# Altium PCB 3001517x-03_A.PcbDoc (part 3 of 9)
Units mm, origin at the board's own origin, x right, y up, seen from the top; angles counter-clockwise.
Board outline 100 x 72 mm, 10 copper layers (Top, GND_2, Signal_3, Signal_4, PWR_5, GND_6, Signal_7, Signal_8, GND_9, Bottom), stack 1.6 mm thick; 602 components, 497 nets, 2372 pads, 1602 vias.
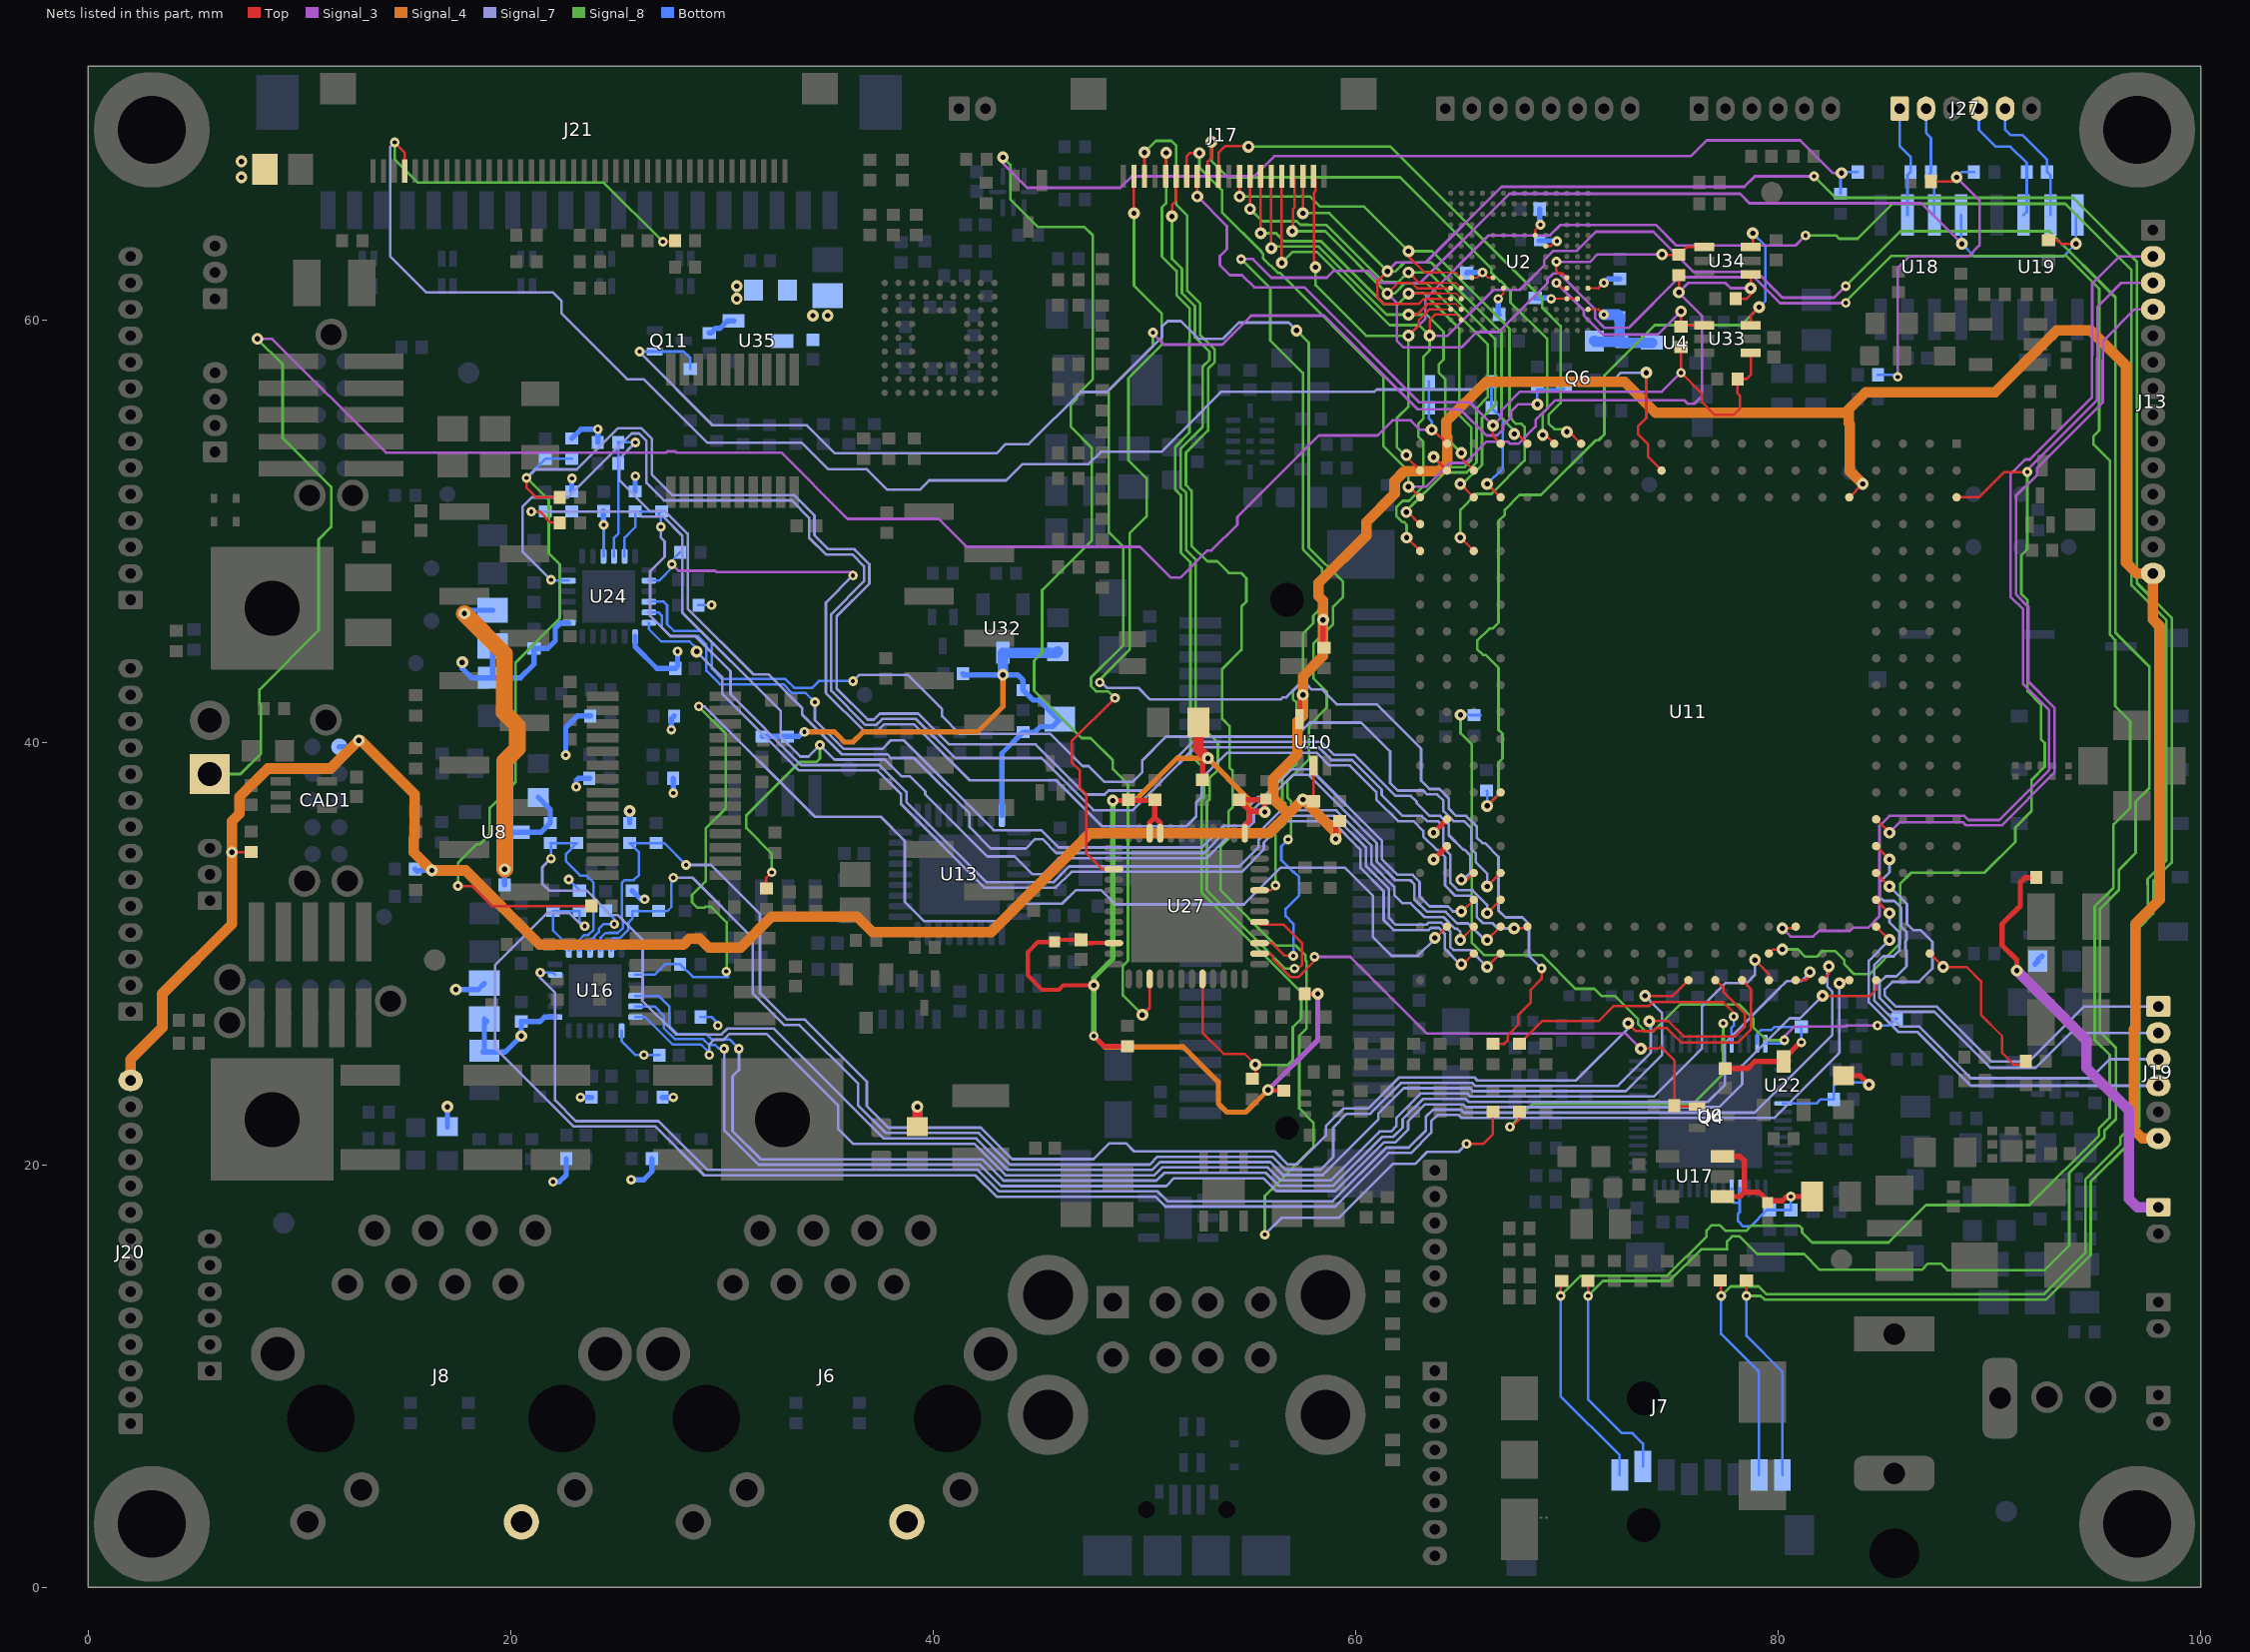
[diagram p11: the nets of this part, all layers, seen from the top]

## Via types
v1: diameter 0.56, hole 0.25, Top to Bottom, tented both sides, 1002 vias
v2: diameter 0.46, hole 0.2, Top to Bottom, tented both sides, 468 vias
v3: diameter 0.457, hole 0.2, Top to Bottom, tented both sides, 132 vias

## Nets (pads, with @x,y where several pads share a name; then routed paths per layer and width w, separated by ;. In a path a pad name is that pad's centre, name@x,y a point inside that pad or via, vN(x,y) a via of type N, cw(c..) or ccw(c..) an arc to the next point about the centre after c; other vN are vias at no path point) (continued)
3V3_CODEC: C87.1 C89.1 C98.2 C102.1 C103.1 C129.2 C149.2 R206.2 U6.6 U6.18 U6.19 U6.55 U17.1 U17.3 U22.D | length 27.4
  Top w0.25: U17.1@77.358,18.5 78.2,18.5 78.4,18.7 ; U17.3@77.358,20.4 78.2,20.4 78.4,20.2 78.4,18.7 ; C149.2@77.5,24.56 78.56,24.56 78.9,24.9 U22.D@80.258,24.9 80.258,25.008 81.05,25.8 v2(81.1,25.8) ; C98.2@81.6,18.5 81.4,18.7 81.2,18.5 v2(80.6,18.5) 80.4,18.5 80.2,18.3 79.5,18.3 79.1,18.7 78.4,18.7 ; R206.2@83.1,24.218 83.882,24.218 v1(84.3,23.8)
  Bottom w0.125: U6.19@77.8,18.88 77.8,18.309 77.909,18.2 78.13,18.2 78.18,18.25 ; U6.18@78.2,18.88 78.18,18.88 78.18,18.25 ; U6.55@79,25.74 79,26.2 79.18,26.38 79.674,26.38 79.814,26.521 81.08,26.521 C89.1@81.1,26.54 ; U6.6@80.23,22.91 81.81,22.91 82,23.1 C87.1@82.64,23.1 82.64,23.74 82.8,23.9 84.2,23.9 v1(84.3,23.8) ; v2(80.6,18.5) C102.1@80.6,17.86 C103.1@79.6,17.86 79.467,17.86 78.7,17.094 78.35,17.094 78.104,17.339 78.104,17.687 78.18,17.763 78.18,18.25 ; v2(81.1,25.8) 81.1,26.499 C89.1@81.101,26.5
3V3_EMMC: C4.2 C5.2 C6.2 C7.2 C24.2 C126.2 C127.2 C128.2 R223.2 U2.C6 U2.E6 U2.F5 U2.J10 U2.K9 U2.M4 U2.N4 U2.P3 U2.P5 U4.D | length 15.5
  Top w0.076: U2.P3@71,60.5 71.5,60.5 ; U2.P5@71,61.5 71.5,61.5
  Top w0.1: U2.C6@65.5,62 65.75,62 v2(66,62.25) 66.25,62 U2.E6@66.5,62 ; v2(66.75,61) 67,61.25 U2.F5@67,61.5 ; U2.J10@68.5,64 68.5,64.25 v2(68.75,64.5) ; U2.K9@69,63.5 69.25,63.5 69.476,63.726 v2(69.524,63.726) ; v2(69.25,61) U2.M4@70,61 U2.N4@70.5,61
  Top w0.125: 71.5,60.5 v2(71.75,60.25) ; 71.5,61.5 v2(71.75,61.75)
  Bottom w0.25: C128.2@65.25,62.21 65.29,62.25 v2(66,62.25) ; v2(66.75,61) 66.75,60.29 C127.2@66.79,60.25 ; C5.2@68.5,61.04 69.21,61.04 v2(69.25,61) ; C126.2@68.69,63.75 69.5,63.75 v2(69.524,63.726) ; C4.2@68.71,65.25 68.71,64.54 v2(68.75,64.5) ; v2(71.75,61.75) 71.94,61.94 C6.2@72.5,61.94
  Bottom w0.5: R223.2@71.3,59 71.34,58.96 C24.2@72.6,58.96 ; v2(71.75,60.25) 72.41,60.25 C7.2@72.5,60.16 72.5,59.06 C24.2@72.6,58.96 ; U4.D@74.02,58.92 72.64,58.92 C24.2@72.6,58.96
3V3_ETH: C26.2 C28.1 C46.1 L2.1 L3.1 R26.1 R27.2 R56.1 R57.1 R58.1 R59.1 R90.1 R158.1 R159.1 R160.1 R161.1 U8.D U16.9 U24.9 | length 34.3
  Signal_4 w0.8: v1(17.8,46.1) 19.7,44.2 19.7,41.4 20.3,40.8 20.3,39.7 19.71,39.11 v1(19.71,34)
  Bottom w0.125: v2(22.742,33.516) 23.25,33.008 R59.1@23.25,32.98 ; U16.9@23.75,30.15 23.75,30.609 24.166,31.024 24.166,31.166 24.4,31.4 v2(24.9,31.4) 24.9,31.64 C28.1@24.5,32.04 ; U24.9@24.389,48.807 24.4,48.818 v2(24.4,50.3) ; R90.1@28.88,46.5 v2(29.5,46.5) ; R26.1@28.98,27 29.5,27 29.8,26.7 v2(29.8,26.6)
  Bottom w0.25: v1(17.4,28.3) 18.45,28.3 L2.1@18.75,28.6 ; v1(17.8,46.1) 17.957,46.257 L3.1@19.139,46.257 ; C26.2@19.71,33.25 v1(19.71,34) 19.71,35.31 20.15,35.75 U8.D@20.375,35.75 21.434,35.75 R58.1@21.873,36.189 21.873,36.827 R27.2@21.3,37.4 ; R161.1@22.889,51.887 22.889,52.489 v2(22.9,52.5) ; R160.1@22.889,54.387 23.322,54.82 v2(24.12,54.82) R158.1@24.12,54.2 ; C46.1@24.389,50.947 24.389,50.311 v2(24.4,50.3) ; R56.1@25.623,36.189 v1(25.623,36.75) ; R57.1@25.75,32.98 26.157,32.573 v2(26.333,32.573) ; R159.1@25.889,51.887 v2@25.889,52.5
  other v2: 25.9,52.6
3V3_INT: C150.2 CAD1.1 J13.14 J19.6 J20.14 R36.2 R149.1 R231.1 R260.1 U10.3 U10.5 U11.E3 | length 190.9
  Top w0.125: v1(6.8,34.8) 7.68,34.8 R36.2@7.7,34.82 ; v1(57.5,37.3) 57.91,37.3 C150.2@58,37.21 U10.5@58,38.9 ; U11.E3@83.37,51.6 v1(84.005,52.235)
  Top w0.25: U10.3@57.35,41.1 57.35,42.1 v1(57.5,42.25) ; R231.1@58.458,44.48 v1(58.458,45.8) ; v1(59.055,35.427) 59.055,36.075 R260.1@59.25,36.27
  Signal_4 w0.5: J20.14@2,23.75 2,25 3.5,26.5 3.5,28.1 6.8,31.4 v1(6.8,34.8) 6.8,36.271 7.157,36.628 7.157,37.417 8.5,38.76 11.46,38.76 v1(12.8,40.1) 12.9,40.1 15.457,37.543 15.457,35.528 15.4,35.471 15.4,34.8 v1(16.261,33.939) 17.861,33.939 21.363,30.436 28.178,30.436 28.449,30.707 28.951,30.707 29.365,30.293 30.885,30.293 32.342,31.75 36.392,31.75 37.131,31.01 42.74,31.01 47.439,35.709 55.909,35.709 56.82,36.62 ; v1(59.055,35.427) 59.055,35.744 v1(57.5,37.3) 56.82,36.62 ; v1(84.005,52.235) 83.392,52.848 83.392,55.047 83.335,55.105 83.343,55.113 83.343,55.772 ; J19.6@98,21.25 97.248,21.25 96.85,21.648 96.85,26.421 96.907,26.478 96.907,31.407 98.062,32.562 98.062,45.5 97.75,45.812 J13.14@97.75,48 96.985,48 96.477,48.508 96.477,57.823 94.8,59.5 93.194,59.5 90.272,56.578 84.149,56.578 83.343,55.772 ; 56.82,36.62 56.1,37.34 56.1,38.278 57.25,39.428 57.25,41 57.5,41.25 v1(57.5,42.25) 57.5,43.125 58.458,44.083 v1(58.458,45.8) 58.458,46.713 58.243,46.928 58.243,47.543 60.5,49.8 60.5,50.429 61.843,51.772 61.843,52.372 62.319,52.848 63.957,52.848 64.342,53.233 64.342,54.459 64.298,54.503 64.298,55.198 66.176,57.077 72.723,57.077 74.2,55.6 83.171,55.6 83.343,55.772
  Bottom w0.25: CAD1.1@11.885,39.79 12.49,39.79 v1(12.8,40.1) ; R149.1@15.472,34 15.572,33.9 15.611,33.939 v1(16.261,33.939)
3V3_IOEXP: C104.2 C105.2 C106.2 C120.2 C122.2 C124.2 R232.1 R247.2 R262.2 R265.2 R280.2 U27.1 U27.9 U27.10 U27.22 | length 61.2
  Top w0.2: v1(47.6,28.5) 46.154,28.5 45.947,28.293 45.155,28.293 44.484,28.964 44.484,30.084 44.948,30.548 C120.2@45.75,30.548 45.854,30.652 C105.2@47,30.652 47.152,30.5 47.533,30.5 47.54,30.507 48.55,30.507 U27.22@48.55,30.5 ; v1(55.85,23.55) 55.88,23.52 R265.2@56.6,23.52
  Top w0.25: v3(47.6,26.1) 48.08,25.62 R262.2@49.2,25.62 ; v1(48.5,37.25) 50.46,37.25 50.482,37.228 50.482,36.443 ; U27.10@50.25,35.7 50.25,36.211 50.482,36.443 ; U27.9@50.75,35.7 50.75,36.175 50.482,36.443 ; R232.1@52.75,38.23 52.75,39 v1(53,39.25) ; U27.1@54.75,35.7 54.75,36.073 54.982,36.305 54.982,36.745 ; C106.2@55.75,37.31 C106.2@55.73,37.29 ; R247.2@57.58,28.1 v1(58.2,28.1) ; 54.982,36.745 55.655,36.745 v1(55.7,36.7) 55.7,37.26 C106.2@55.73,37.29 ; 54.982,36.745 54.5,37.227 C104.2@54.5,37.29 C106.2@55.73,37.29
  Top w0.5: R280.2@52.55,40.95 52.55,39.7 v1(53,39.25)
  Signal_3 w0.25: v1(55.85,23.55) 58.2,25.9 v1(58.2,28.1)
  Signal_8 w0.25: v3(47.6,26.1) v1(47.6,28.5) 47.6,28.85 48.5,29.75 48.5,30.3 v1(48.5,37.25)
  Signal_4 w0.25: v3(47.6,26.1) 48.119,25.581 51.841,25.581 53.5,23.922 53.5,22.9 53.9,22.5 54.8,22.5 v1(55.85,23.55) ; v1(48.5,37.25) 49.55,37.25 51.55,39.25 v1(53,39.25) 54.901,37.349 54.901,36.973 55.174,36.7 v1(55.7,36.7)
3V3_USB: C154.2 L17.2 R65.2 R66.2 R68.2 R82.2 R242.1 U13.27 U32.D | length 29.7
  Signal_4 w0.25: v2(33.9,40.5) 35.318,40.5 35.518,40.3 ; 35.518,40.3 35.8,40.018 36.2,40.018 36.682,40.5 42.1,40.5 43.3,41.7 v1(43.3,43.2)
  Bottom w0.125: v2@33.848,40.5 v2(33.9,40.5)
  Bottom w0.25: R65.2@31.9,40.28 R66.2@33.1,40.28 33.628,40.28 v2@33.848,40.5 ; C154.2@41.41,43.25 41.46,43.2 v1(43.3,43.2) 44,43.2 44.25,42.95 R242.1@44.25,42.48 44.73,42 45,42 45.9,41.1 L17.2@46,41.1 45.65,40.75 45.073,40.75 44.803,40.48 R68.2@44.25,40.48 43.25,39.48 U13.27@43.25,36.55
  Bottom w0.5: v1(43.3,43.2) v1(43.3,43.2) U32.D@43.299,44.239 45.839,44.239 R82.2@45.9,44.3
5V: J5.1 R12.2 R21.2 R250.1 R251.1 U11.Y15 U11.Y16 U35.S | length 24
  Top w0.25: v1(63.685,34.455) U11.Y16@64.32,35.09 ; v1(63.685,35.725) U11.Y15@64.32,36.36 ; v1(91.3,29.2) 91.3,29.7 90.6,30.4 90.6,31.4 91.463,32.263 91.463,33.363 91.7,33.6 R12.2@92.22,33.6
  Signal_3 w0.5: v1(91.3,29.2) 94.6,25.9 94.6,24.592 96.6,22.592 96.6,18.4 97,18 J5.1@98,18
  Bottom w0.25: R251.1@29.4,59.38 29.48,59.38 29.7,59.6 29.9,59.6 30.25,59.95 U35.S@30.55,59.95 ; R21.2@92.15,29.5 R21.2@92.3,29.65 92.3,29.7 R21.2@92.5,29.9
  other v1: 30.7,61 30.7,61.6
5V_DISPLAY: C158.2 L18.1 L34.1 R250.2 U35.D
  other v1: 34.3,60.2 35,60.2 7.25,66.75 7.25,67.5
AUD_I2C_SCL: R114.2 U6.51 | length 15.4
  Top w0.119: v2(67.3,21.8) 67.388,21.8 67.75,22.162 R114.2@67.75,22.52
  Signal_8 w0.127: v2(67.3,21.8) 68.4,22.9 75.984,22.9 77.4,24.316 v3(77.4,26.7)
  Bottom w0.119: U6.51@77.4,25.74 v3(77.4,26.7)
AUD_I2C_SDA: R115.2 U6.52 | length 12.8
  Top w0.119: R115.2@67.75,25.73 68.82,26.8 71.5,26.8 72.231,27.53 73.894,27.53 74.064,27.7 77.4,27.7 78,27.1 77.928,27.028 v3(77.898,27.028)
  Bottom w0.119: U6.52@77.8,25.74 77.8,26.5 77.898,26.598 v3(77.898,27.028)
AUD_INT#: R93.2 R272.2 U6.56 | length 37.4
  Signal_3 w0.127: v2(80.3,25.9) 80.3,26.1 80.747,26.547 83.205,26.547 83.258,26.6 v3(84.7,26.6)
  Signal_8 w0.127: v1(64.967,41.3) 64.967,40.433 65.5,39.9 65.5,30.5 66.065,29.935 68.809,29.935 70.407,28.338 71.303,28.338 71.641,28 72.265,28 73.37,26.895 73.37,26.664 73.705,26.329 74.095,26.329 75.349,27.584 78.168,27.584 78.825,26.926 78.825,26.521 79.446,25.9 v2(80.3,25.9)
  Bottom w0.119: v1(64.967,41.3) 65.9,41.3 65.92,41.28 R272.2@65.6,41.28 R272.2@65.5,41.28 ; U6.56@79.4,25.74 80.14,25.74 v2(80.3,25.9) ; v3(84.7,26.6) 85.24,26.6 85.58,26.94 R93.2@85.62,26.9
AUD_PWR/IO28: Q4.G R132.2 U27.38 | length 26.1
  Top w0.119: U27.38@55.45,30 55.957,30 56.09,29.866 56.09,29.723 56.928,28.885 57.272,28.885 58.05,29.663 v3(58.05,29.85) ; v1(73.5,25.5) 74.335,25.5 74.435,25.6 75.1,24.935 75.1,22.82 R132.2@75.08,22.8 75.12,22.76 Q4.G@76.16,22.76
  Signal_3 w0.127: v3(58.05,29.85) 59.75,29.85 63.382,26.218 72.782,26.218 v1(73.5,25.5)
AVDD1: C15.2 C16.2 C17.1 J6.11 L2.2 R44.2 R45.2 R46.2 R47.2 R48.2 U16.1 U16.19 | length 14.1
  Top w0.5: R48.2@39.25,21.8 v1(39.25,22.75)
  Bottom w0.125: U16.19@25.25,26.35 25.25,25.85 25.9,25.2 v2(26.3,25.2) C16.2@27.04,25.2
  Bottom w0.25: L2.2@18.86,26.79 L2.2@18.75,26.9 C15.2@18.75,25.4 18.693,25.343 19.743,25.343 v1(20.5,26.1) C17.1@20.5,26.79 21.39,26.79 21.6,27 U16.1@22.1,27 ; v3(22,19.2) 22.3,19.2 22.62,19.52 R46.2@22.62,20.3 ; v3(23.3,23.2) R44.2@23.82,23.2 ; v3(25.7,19.3) 26.3,19.3 26.68,19.68 R47.2@26.68,20.3 ; R45.2@27.18,23.2 v3(27.7,23.2)
AVDD2: C43.2 C44.2 C45.1 J8.11 L3.2 R79.2 R85.2 R86.2 R87.2 R88.2 U24.1 U24.19 | length 18.5
  Bottom w0.25: R79.2@17,21.8 v1(17,22.75) ; v1(17.7,43.789) 17.7,43.5 18.143,43.057 C43.2@19.139,43.057 ; L3.2@19.139,44.557 C43.2@19.139,43.057 ; v3(22.6,39.4) 22.6,40.7 23.15,41.25 R85.2@23.77,41.25 ; U24.1@22.739,45.657 22.357,45.657 22.1,45.4 22.1,44.8 21.747,44.447 21.1,44.447 21.1,43.7 20.457,43.057 C43.2@19.139,43.057 ; v2(23.1,37.9) 23.1,38.2 23.2,38.3 R87.2@23.72,38.3 ; U24.19@25.889,45.007 25.889,44.529 26.918,43.5 C44.2@27.79,43.5 27.9,43.61 v2(27.9,44.3) ; v3(27.6,40.6) 27.6,41.12 R86.2@27.73,41.25 ; R88.2@27.68,38.3 27.7,38.28 v2(27.7,37.6)
BCKL_PWM: J21.37 R258.1 U11.M2 | length 94.7
  Top w0.125: v2(14.5,68.4) 14.976,67.924 J21.37@14.976,67.05 ; v2(27.2,63.7) 27.72,63.7 R258.1@27.77,63.75 ; v1(73.758,57.5) 73.758,55.352 73.375,54.969 73.375,54.581 73.845,54.111 73.845,53.505 U11.M2@74.48,52.87
  Signal_8 w0.125: v2(14.5,68.4) 14.5,67.6 15.6,66.5 24.4,66.5 v2(27.2,63.7)
  Signal_7 w0.125: v2(14.5,68.4) 14.3,68.2 14.3,63 16,61.3 22,61.3 22.395,60.905 22.395,60.31 25.512,57.193 26.295,57.193 29.307,54.182 33.774,54.182 35.027,52.929 36.864,52.929 37.834,51.959 39.359,51.959 39.8,52.4 43.295,52.4 43.448,52.4 44.221,53.174 44.779,53.174 47.358,53.173 47.94,53.756 50.8,53.756 52.048,55.004 53.643,56.599 60.883,56.599 60.99,56.706 66.1,56.706 66.596,57.202 72.26,57.202 72.558,57.5 v1(73.758,57.5)
BOOT_MODE0: R24.2 R28.1 U11.V3 | length 6.3
  Top w0.125: v1(66.225,52.235) U11.V3@66.86,51.6
  Bottom w0.125: v1(66.225,52.235) 66.969,52.979 66.969,55.301 R24.2@66.43,55.84 R28.1@66.43,57.09
BOOT_MODE1: J10.1 R25.2 R29.1 U11.Y1 | length 92.5
  Top w0.125: v1(63.6,54.8) 63.66,54.8 U11.Y1@64.32,54.14
  Signal_3 w0.125: v1(8,59.1) 8.7,59.1 14.08,53.72 27.356,53.72 27.405,53.769 27.794,53.769 27.844,53.72 32.804,53.72 35.87,50.653 35.873,50.653 35.944,50.582 40.264,50.582 41.589,49.257 47.39,49.257 49.787,49.257 51.244,47.8 51.7,47.8 52.98,49.08 53.174,49.08 54.4,50.307 54.4,50.675 58.255,54.53 61.03,54.53 61.745,55.245 62.609,55.245 63.054,54.8 v1(63.6,54.8)
  Signal_8 w0.125: J10.1@5.75,38.5 7.2,38.5 8.17,39.47 8.17,41.794 8.1,41.864 8.1,42.5 10.9,45.3 10.9,49.6 11.5,50.2 11.5,52.1 9.2,54.4 9.2,57.9 v1(8,59.1)
  Bottom w0.125: R29.1@63.47,57.09 R25.2@63.47,55.84 63.47,55.33 63.6,55.2 v1(63.6,54.8)
BT_EN: J13.2 U11.G19 | length 48.4
  Top w0.119: v1(80.2,31.2) U11.G19@80.83,31.2
  Signal_3 w0.127: v1@80.2,31.101 v1(80.2,31.2) 80.59,30.81 81.66,30.81 81.927,31.077 83.396,31.077 83.544,31.225 84.25,31.225 84.8,31.775 84.8,36.05 85.275,36.525 88.81,36.525 89.005,36.329 90.474,36.329 92.825,38.68 92.825,41.534 91.6,42.759 91.6,46.3 91.002,46.898 91.002,52.695 91.7,53.392 91.918,53.392 94.853,56.327 94.853,58.302 94.873,58.321 94.873,61.723 96.15,63 J13.2@97.75,63
BT_LED: R23.2 U11.B20 | length 8.2
  Top w0.119: U11.B20@87.18,30.01 v1(87.815,29.375) 88.925,29.375 89.6,28.7 89.6,27.1 90.6,26.1 90.6,25.3 91.15,24.75 R23.2@91.77,24.75
BT_UART1_CTS: J19.2 U11.D16 | length 24.6
  Top w0.119: U11.D16@84.64,35.09 v1(85.275,34.455)
  Signal_7 w0.127: v1(85.275,34.455) 85.275,33.85 84.805,33.38 84.805,32.695 85,32.5 85.5,32.5 85.821,32.179 85.821,31.295 86.075,31.041 86.075,30.64 86.03,30.595 86.03,30.205 86.075,30.16 86.075,29.409 85.595,28.929 85.095,28.929 84.799,28.634 84.799,27.906 85.46,27.246 87.395,27.246 90.041,24.6 92.2,24.6 93.85,26.25 J19.2@98,26.25
BT_UART1_RTS#: J19.4 U11.D19 | length 19.6
  Top w0.119: U11.D19@84.64,31.28 v1(85.275,30.645)
  Signal_7 w0.127: v1(85.275,30.645) 84.291,29.661 84.291,27.696 85.697,26.29 86.585,26.29 89.129,23.746 97.996,23.746 J19.4@98,23.75
BT_UART1_RX: J19.3 U11.D18 | length 21.4
  Top w0.119: U11.D18@84.64,32.55 v1(85.275,31.915)
  Signal_7 w0.127: v1(85.275,31.915) 85.275,31.481 85.746,31.011 85.746,30.146 85.47,29.87 84.97,29.87 84.545,29.445 84.545,27.801 85.802,26.544 86.69,26.544 89.134,24.1 94.8,24.1 95.7,25 J19.3@98,25
BT_UART1_TX: J19.1 U11.D17 | length 24.1
  Top w0.119: U11.D17@84.64,33.82 v1(85.275,33.185)
  Signal_7 w0.127: v1(85.275,33.185) 86.103,32.357 86.103,31.405 86.392,31.116 86.74,31.116 87.3,30.555 87.3,29.3 86.67,28.67 85.405,28.67 85.053,28.319 85.053,28.012 85.565,27.5 87.5,27.5 90.1,24.9 91.9,24.9 94.5,27.5 J19.1@98,27.5
BT_WAKEUP_HOST: J13.3 U11.A3 U11.H20 | length 51.6
  Top w0.119: U11.H20@79.56,30.01 79.75,30.2 v1(80.2,30.2) ; U11.A3@88.45,51.6 89.5,51.6 90.7,52.8 v2(91.8,52.8)
  Signal_3 w0.127: v2(91.8,52.8) 91.8,52.891 95.107,56.198 95.107,58.197 95.127,58.216 95.127,60.627 96.25,61.75 J13.3@97.75,61.75
  Signal_8 w0.127: v1(80.2,30.2) 80.934,30.2 81.278,29.856 81.831,29.856 82.1,30.124 82.7,30.124 83.124,29.7 83.124,29.51 83.605,29.029 84.325,29.029 85.776,30.48 85.776,33.306 86.3,33.831 89.773,33.831 91.225,35.283 91.225,35.973 91.997,36.745 91.997,38.222 92.62,38.845 92.62,39.974 92.443,40.151 92.443,41.795 91.813,42.425 91.813,46.72 91.51,47.023 91.51,48.846 91.8,49.136 v2(91.8,52.8)
BT_WAKEUP_SLAVE: J13.4 U11.D15 | length 35.9
  Top w0.119: U11.D15@84.64,36.36 v1(85.275,35.725)
  Signal_3 w0.127: v1(85.275,35.725) 85.772,36.222 88.753,36.222 88.9,36.075 90.579,36.075 93.079,38.575 93.079,41.639 91.854,42.864 91.854,46.405 91.256,47.003 91.256,51.662 92.261,52.666 92.261,52.993 95.361,56.093 95.361,58.092 95.381,58.111 95.381,59.002 96.878,60.5 J13.4@97.75,60.5
CAN1_H: J27.2 R104.2 U18.7 | length 5.2
  Bottom w0.125: J27.2@87,70 87,68.85 87.23,68.62 R104.2@87.23,67 87.2,66.97 87.2,66.4 87.395,66.205 U18.7@87.395,64.97
CAN1_L: J27.1 R104.1 U18.6 | length 5.3
  Bottom w0.125: J27.1@85.75,70 85.75,68.25 86.27,67.73 R104.1@86.27,67 86.125,66.855 U18.6@86.125,64.97
CAN2_H: J27.5 R116.2 U19.7 | length 6.2
  Bottom w0.125: J27.5@90.75,70 90.75,69 91,68.75 91.55,68.75 92.73,67.57 R116.2@92.73,67 92.895,66.835 U19.7@92.895,64.97
CAN2_L: J27.4 R116.1 U19.6 | length 6.4
  Bottom w0.125: J27.4@89.5,70 89.5,69 90.3,68.2 91,68.2 91.77,67.43 R116.1@91.77,67 91.77,65.115 U19.6@91.625,64.97
CAN_EN1/IO17: R40.2 R263.2 U27.27 | length 93.9
  Top w0.127: v1(49.9,27.1) 50.25,27.45 U27.27@50.25,28.8
  Signal_3 w0.127: v1(43.3,67.7) 43.3,67.4 44.45,66.25 48.85,66.25 49.4,66.8 55.2,66.8 56.148,67.748 75.868,67.748 76.62,68.5 81.05,68.5 82.6,66.95 v1(83,66.95)
  Signal_8 w0.127: v1(43.3,67.7) 43.65,67.35 43.65,65.7 44.95,64.4 47.15,64.4 47.554,63.995 47.554,57.204 46.8,56.45 46.8,56.271 46.514,55.986 46.514,54.936 47.5,53.95 47.5,49.55 45.158,47.208 45.158,44.24 44.78,43.861 44.78,42.449 47.028,40.2 47.45,40.2 48.5,39.15 48.5,38.728 48.951,38.278 48.954,38.278 49.223,38.009 49.223,29.67 48.976,29.423 48.976,28.024 v1(49.9,27.1)
  Bottom w0.127: R40.2@82.95,65.98 82.95,66.9 v1(83,66.95) 83.05,67 R263.2@83.77,67
CAN_EN2/IO15: R264.2 R281.2 R282.1 | length 16.3
  Top w0.125: R281.2@87.23,66.55 88.25,66.55 v1(88.45,66.75)
  Signal_3 w0.125: v2(85.662,57.3) 85.662,62.462 86.2,63 89,63 89.53,63.53 89.53,65.67 v1(88.45,66.75)
  Bottom w0.125: R282.1@84.73,57.4 85.562,57.4 v2(85.662,57.3)
  Bottom w0.127: v1(88.45,66.75) 88.7,67 R264.2@89.27,67
CAN_STBY/IO34: R267.1 U18.8 U19.8 U27.44 | length 80.9
  Top w0.119: U27.44@55.45,33 55.975,33 v3(56.201,33.226) ; R267.1@92.8,63.78 93.22,63.78 93.4,63.6 v1(94.1,63.6)
  Signal_3 w0.127: v2(54.578,62.878) 55.133,62.878 56.011,62 58.634,62 58.954,62.321 60.58,62.321 61.15,61.75 63.05,61.75 67.271,65.971 78.195,65.971 78.64,65.526 86.775,65.526 v1(88.7,63.6)
  Signal_8 w0.127: v2(54.578,62.878) 55.954,61.502 55.954,59.03 57.5,57.484 57.5,49.154 57.527,49.126 57.527,49.115 58.4,48.242 58.4,46.408 57.987,45.995 57.987,45.636 57.5,45.148 57.5,42.915 57.029,42.445 57.029,42.055 57.214,41.871 57.214,40.973 57.196,40.955 57.196,38.971 56.527,38.302 56.527,37.256 56.678,37.105 56.678,36.188 56.201,35.71 v3(56.201,33.226)
  Bottom w0.119: U18.8@88.665,64.97 88.665,63.635 v1(88.7,63.6) 89.3,63 93.5,63 v1(94.1,63.6) 94.1,64.905 U19.8@94.165,64.97
CSI_DATA02: J7.7 J17.2 R34.1 U2.A3 U11.AA2 | length 137.2
  Top w0.076: 64,60.5 U2.A3@64.5,60.5
  Top w0.119: J17.2@58,66.8 58.1,66.7 58.1,66.103 58.033,66.036 58.033,62.567 v1(58.1,62.5) ; v1(62.4,53.6) 62.4,53.52 U11.AA2@63.05,52.87 ; v1(62.5,59.25) 63,59.75 63,60 63.5,60.5 64,60.5 ; R34.1@77.25,14.52 77.3,14.47 v2(77.3,13.8)
  Signal_3 w0.127: v1(62.5,59.25) 63.3,60.05 63.3,61 66.3,64 69.204,64 69.704,64.5 74.2,64.5 75.176,63.524 80.824,63.524 v2(81.3,64)
  Signal_8 w0.127: v1(58.1,62.5) 58.1,61.646 60.496,59.25 v1(62.5,59.25) 62.5,55.9 61.945,55.345 61.945,53.976 62.32,53.6 v1(62.4,53.6) ; v2(77.3,13.8) 77.75,14.25 79.085,14.25 79.459,13.875 92.582,13.875 94.546,15.84 94.546,19.309 96.211,20.974 96.211,21.309 96.85,21.948 96.85,31.35 97.5,32 97.5,33.25 97.496,33.254 97.496,33.528 98.383,34.415 98.383,45.785 96.731,47.438 96.731,62.353 93.584,65.5 85.422,65.5 83.766,63.843 82.891,63.843 82.735,64 v2(81.3,64)
  Bottom w0.119: v2(77.3,13.8) 77.3,12 79.1,10.2 J7.7@79.1,5.325
CSI_DATA03: J7.8 J17.3 R33.1 U2.A4 U11.U1 | length 140.3
  Top w0.076: 64,61 U2.A4@64.5,61
  Top w0.119: v1(57.5,65.053) J17.3@57.5,66.8 ; v1(61.5,62.3) 61.033,61.834 61.033,61.057 61.34,60.75 62.975,60.75 63.225,61 64,61 ; v1(67.503,54.603) 67.667,54.603 U11.U1@68.13,54.14 ; v2(78.5,13.8) R33.1@78.5,14.52
  Signal_3 w0.127: v1(61.5,62.3) 61.92,62.72 63.32,62.72 66.9,66.3 78.4,66.3 78.9,66.8 v2(81.7,66.8)
  Signal_8 w0.127: v1(57.5,65.053) 58.747,65.053 v1(61.5,62.3) 61.885,62.3 62.305,62.72 63.579,62.72 66.9,59.4 66.9,55.37 67.503,54.767 v1(67.503,54.603) ; v2(78.5,13.8) 79.175,13.8 79.354,13.621 92.687,13.621 94.8,15.735 94.8,19.204 96.465,20.869 96.465,21.203 97.104,21.843 97.104,31.245 97.758,31.899 97.758,33.43 98.637,34.31 98.637,45.89 96.985,47.543 96.985,62.765 93.97,65.78 82.721,65.78 v2(81.7,66.8)
  Bottom w0.119: v2(78.5,13.8) 78.5,11.9 80.2,10.2 J7.8@80.2,5.325
CSI_DATA04: J7.1 J17.4 R32.1 U2.A5 U11.AA4 | length 152.9
  Top w0.076: 64,61.5 U2.A5@64.5,61.5
  Top w0.119: v1(57,64.2) 57.03,64.23 57.03,65.247 57.1,65.317 57.1,66.7 J17.4@57,66.8 ; v1(61.5,61.25) 62,61.75 62.66,61.75 62.91,61.5 64,61.5 ; v1(62.4,50.9) 62.48,50.9 U11.AA4@63.05,50.33 ; v2(69.7,13.8) 69.7,14.45 R32.1@69.75,14.5
  Signal_3 w0.127: v1(61.5,61.25) 61.957,60.793 61.957,59.002 62.259,58.7 65,58.7 65.723,59.423 66.768,59.423 69.08,61.735 69.08,61.924 69.355,62.2 69.645,62.2 71.329,60.515 71.329,60.076 71.782,59.623 72.923,59.623 75.321,62.021 78.87,62.021 80.095,60.796 83.196,60.796 v2(83.2,60.8)
  Signal_8 w0.127: v1(57,64.2) 58.55,64.2 v1(61.5,61.25) 61.835,61.25 62.305,61.72 63.38,61.72 66.25,58.85 66.25,56.34 65.724,55.814 65.724,53.25 65.255,52.781 64.231,52.781 62.4,50.95 v1(62.4,50.9) ; v2(69.7,13.8) 70.658,14.758 74.75,14.758 76.608,16.616 76.608,16.9 76.855,17.146 77.244,17.146 77.51,16.879 78.485,16.879 78.726,17.12 80.99,17.12 81.129,16.981 81.129,16.805 81.605,16.329 85.229,16.329 87,18.1 91.9,18.1 95.195,21.395 95.195,21.729 95.692,22.227 95.692,25.208 94.988,25.912 94.988,32.231 95.879,33.122 95.879,36.116 96.662,36.899 96.662,41.01 95.959,41.713 95.959,44.845 95.715,45.089 95.715,53.32 94.93,54.105 94.93,54.495 95.196,54.761 95.196,61.48 93.647,63.028 85.369,63.028 83.2,60.859 v2(83.2,60.8)
  Bottom w0.119: v2(69.7,13.8) 69.7,9.05 72.5,6.25 J7.1@72.5,5.325
CSI_DATA05: J7.2 J17.5 R31.1 U2.B2 U11.AA5 | length 149.2
  Top w0.076: 64,60.25 64.75,60.25 U2.B2@65,60
  Top w0.119: v1(56.5,62.7) J17.5@56.5,66.8 ; v1(62.415,49.695) U11.AA5@63.05,49.06 ; v1(63.5,59.25) 63.5,60 63.75,60.25 64,60.25 ; v2(71,13.8) R31.1@71,14.5
  Signal_3 w0.127: v1(63.5,59.25) 64.345,59.25 66.515,61.42 67.765,61.42 68.92,62.576 68.92,62.821 69.37,63.27 70.47,63.27 71.37,64.17 74.095,64.17 75.99,62.275 78.975,62.275 80.2,61.05 82.65,61.05 v2(83.2,61.6)
  Signal_8 w0.127: v1(56.5,62.7) 57.02,63.22 58.146,63.22 61.616,59.75 63,59.75 v1(63.5,59.25) 63.5,58.55 63.2,58.25 63.2,55.315 62.961,55.075 62.961,54.475 63.2,54.235 63.2,52.109 62.526,51.436 62.22,51.436 61.929,51.145 61.929,50.705 62.205,50.429 62.285,50.429 62.415,50.3 v1(62.415,49.695) ; v2(71,13.8) 71.704,14.504 74.855,14.504 76.351,16 77.605,16 77.579,16.026 77.579,16.374 77.826,16.62 78.174,16.62 79.015,15.779 81.221,15.779 81.967,15.033 86.809,15.033 87.1,15.324 87.7,15.324 88.009,15.016 92.625,15.016 93.784,16.175 93.784,19.625 95.449,21.29 95.449,21.624 95.992,22.167 95.992,25.54 95.242,26.29 95.242,32.126 96.133,33.017 96.133,33.968 96.93,34.764 96.93,37.197 97.575,37.842 97.575,43.588 95.969,45.195 95.969,61.066 92.835,64.2 85.8,64.2 v2(83.2,61.6)
  Bottom w0.119: v2(71,13.8) 71,8.9 72.6,7.3 73.1,7.3 73.6,6.8 J7.2@73.6,5.725
CSI_DATA06: J17.6 U2.B3 U11.W2 | length 23.4
  Top w0.076: 64,60.75 64.75,60.75 U2.B3@65,60.5
  Top w0.119: v1(56,63.4) J17.6@56,66.8 ; v1(62.5,60.25) 62.9,60.25 63.4,60.75 64,60.75 ; v1(65,53.7) 65,53.46 U11.W2@65.59,52.87
  Signal_8 w0.127: v1(56,63.4) 56.074,63.474 58.251,63.474 61.475,60.25 v1(62.5,60.25) 63.35,60.25 64.163,59.437 64.163,58.129 63.93,57.895 63.93,57.505 64.25,57.185 64.25,54.45 v1(65,53.7)
CSI_DATA07: J17.7 U2.B4 U11.Y2 | length 26.5
  Top w0.076: 64,61.25 64.75,61.25 U2.B4@65,61
  Top w0.119: v1(55.5,64.1) J17.7@55.5,66.8 ; v1(62.5,61.25) 64,61.25 ; v1(63.685,53.505) U11.Y2@64.32,52.87
  Signal_8 w0.127: v1(55.5,64.1) 56.229,64.1 56.6,63.728 58.356,63.728 61.335,60.75 62,60.75 v1(62.5,61.25) 63.25,61.25 64.9,59.6 64.9,55.495 65.47,54.925 65.47,53.355 65.15,53.035 64.156,53.035 v1(63.685,53.505)
CSI_DATA08: J17.8 U2.B5 U11.W3 | length 27.4
  Top w0.076: 64,61.75 64.75,61.75 U2.B5@65,61.5
  Top w0.119: v1(55,65.25) J17.8@55,66.8 ; v1(62.5,62.25) 62.508,62.25 63.008,61.75 64,61.75 ; v1(64.955,52.235) U11.W3@65.59,51.6
  Signal_8 w0.127: v1(55,65.25) 55.579,64.671 57.211,64.671 57.38,64.502 57.748,64.502 57.75,64.5 58.6,64.5 58.646,64.454 58.655,64.454 61.309,61.8 62.025,61.8 62.475,62.25 v1(62.5,62.25) 63.45,62.25 66.6,59.1 66.6,55.983 65.978,55.361 65.978,53.145 65.069,52.235 v1(64.955,52.235)
CSI_DATA09: J17.9 U2.B6 U11.W5 | length 32.4
  Top w0.076: 64,62.25 64.75,62.25 U2.B6@65,62
  Top w0.119: v1(54.5,65.843) J17.9@54.5,66.8 ; v1(62.5,63.25) 62.5,63 63.25,62.25 64,62.25 ; v1(64.955,49.695) U11.W5@65.59,49.06
  Signal_8 w0.127: v1(54.5,65.843) 57.835,65.843 58.305,65.373 60.377,65.373 v1(62.5,63.25) 63.609,63.25 67.279,59.58 67.279,55.402 67.599,55.082 67.853,55.082 68,54.935 68,53.345 66.42,51.765 65.707,51.765 64.955,51.013 v1(64.955,49.695)
CSI_GPIO/IO31: J17.15 U27.41 | length 45.8
  Top w0.119: v1(51.3,64.9) 51.314,64.914 51.314,65.465 51.5,65.65 J17.15@51.5,66.8 ; U27.41@55.45,31.5 55.45,31.384 56.569,31.384 57.466,30.486 57.466,29.477 57.289,29.3 v3(57.1,29.3)
  Signal_8 w0.127: v1(51.3,64.9) 51.3,62.887 51.771,62.415 51.771,61.275 52.389,60.658 52.389,59.177 53.07,58.495 53.07,58.105 52.754,57.789 52.754,54.929 51.708,53.883 51.708,52.076 51.978,51.805 51.978,49.085 52.429,48.635 52.429,41.031 53.475,39.985 53.475,38.7 53.078,38.304 53.078,37.295 52.955,37.171 52.955,32.994 56.648,29.3 v3(57.1,29.3)
CSI_HSYNC: J17.13 R243.1 R244.1 U11.V1 U33.4 | length 40.5
  Top w0.119: v1(52.5,65.843) J17.13@52.5,66.8 ; v1(66.5,55) 66.5,54.5 U11.V1@66.86,54.14 ; R244.1@75.4,58.72 v2(75.4,57.5) 76.4,56.5 76.4,56.1 77,55.5 77.9,55.5 78.2,55.8 78.2,56.4 78.08,56.52 R243.1@78.08,57.2 78.5,57.2 78.7,57.4 U33.4@78.7,58.45
  Signal_3 w0.127: v1(52.5,65.843) 53.9,64.443 53.9,63.35 53.57,63.02 53.57,62.6 54.05,62.12 54.618,62.12 55.194,61.544 57.556,61.544 63,56.1 65.4,56.1 v1(66.5,55) 66.9,55.4 66.9,55.721 67.779,56.6 74.5,56.6 v2(75.4,57.5)
CSI_I2C_SCL: J17.18 R108.2 | length 76
  Top w0.119: J17.18@50,66.8 v1(50,67.925) ; v2(65.25,21) 66.05,21 66.5,21.45 R108.2@66.5,22.52
  Signal_8 w0.127: v1(50,67.925) 50.55,68.475 51.275,68.475 51.496,68.254 51.496,65.464 52.025,64.934 52.025,61.38 52.643,60.763 52.643,59.282 53.324,58.6 53.324,58 53.008,57.684 53.008,54.758 51.962,53.712 51.962,52.181 52.232,51.91 52.232,49.314 52.975,48.571 53.445,48.571 53.995,48.02 54.574,48.02 54.82,47.774 54.82,46.661 54.592,46.433 54.592,44.388 53.675,43.471 53.675,41.125 54.03,40.771 54.03,38.805 54.17,38.664 54.17,36.911 53.98,36.72 53.98,35.426 53.6,35.046 53.6,33.007 56.226,30.381 57.164,30.381 57.631,29.914 57.631,29.676 57.674,29.633 57.674,26.461 57.328,26.115 57.328,22.677 58,22.005 58,20.835 55.7,18.535 v3(55.7,16.7)
  Signal_7 w0.127: v3(55.7,16.7) 56.489,17.489 59.204,17.489 61.77,20.055 62.828,20.055 63.39,20.617 64.867,20.617 v2(65.25,21)
CSI_I2C_SDA: J17.19 R111.2 | length 62.2
  Top w0.119: v1(49.5,65.053) J17.19@49.5,66.8 ; R111.2@66.5,25.73 67.03,25.73 67.2,25.9 67.2,26.144 67.7,26.644 67.7,27.1 68.295,27.695 68.295,28.299 68.8,28.804 v2(68.8,29.3)
  Signal_8 w0.127: v3(47.89,42.838) 47.89,42.974 47.884,42.979 49.3,44.395 49.3,49.9 50.1,50.7 50.1,52.5 49.243,53.357 49.243,57.243 50.82,58.82 50.82,60.304 49.5,61.624 v1(49.5,65.053)
  Signal_7 w0.127: v3@47.9,42.8 48.005,42.8 48.226,42.579 49.721,42.579 50.271,42.029 56.446,42.029 56.548,42.132 56.716,42.132 57.305,42.72 57.695,42.72 57.903,42.512 58.388,42.512 59.096,41.804 60.996,41.804 63.1,39.7 63.1,38.185 63.49,37.795 63.965,37.795 64.41,37.35 64.41,36.875 64.76,36.525 65.235,36.525 65.73,36.03 65.73,35.505 66.005,35.23 66.116,35.23 66.764,34.581 66.764,32.036 67.088,31.712 67.888,31.712 68.2,31.4 68.2,29.9 v2(68.8,29.3)
CSI_MCLK: J17.11 U11.R1 | length 28
  Top w0.119: J17.11@53.5,66.8 53.5,67.917 53.807,68.223 54.902,68.223 v1(54.925,68.2) ; v1(70,54.7) 70.11,54.7 U11.R1@70.67,54.14
  Signal_8 w0.127: v1(54.925,68.2) 61.645,68.2 68.83,61.015 68.83,60.58 69.7,59.709 69.7,56.065 69.129,55.495 69.129,55.105 69.405,54.829 69.909,54.829 70.019,54.719 v1(70,54.7)
CSI_PIXCLK: J17.12 U11.T1 | length 27.8
  Top w0.119: J17.12@53,66.8 53,67.5 53.169,67.669 v1(53.17,68.43) ; v1(68.853,54.553) 68.893,54.553 68.94,54.6 U11.T1@69.4,54.14 ; v1(53.17,68.43) v1(53.17,68.43)
  Signal_8 w0.127: v1(53.17,68.43) 53.17,67.53 53.949,66.751 62.094,66.751 66.42,62.424 66.42,62.235 66.826,61.83 66.871,61.83 67.329,61.371 67.329,60.826 69.07,59.085 69.07,55.805 68.853,55.588 v1(68.853,54.553)
CSI_PWDN/IO22: J17.16 R121.1 U27.32 | length 55.8
  Top w0.119: J17.16@51,66.8 51,67.886 v1(51.025,67.911) ; U27.32@52.75,28.8 52.75,26.257 53.757,25.25 54.75,25.25 v1(55.25,24.75) R121.1@55.25,24.23
  Signal_8 w0.127: v1(51.025,67.911) 51.025,65.525 50.829,65.329 50.829,62.998 51.517,62.31 51.517,61.169 52.135,60.552 52.135,59.071 52.129,59.066 52.129,54.664 51.454,53.988 51.454,51.97 51.724,51.7 51.724,48.979 52.175,48.529 52.175,39.41 52.824,38.76 52.824,37.4 52.701,37.276 52.701,32.888 57.42,28.168 57.42,26.926 57.02,26.525 57.02,24.975 56.774,24.729 55.271,24.729 v1(55.25,24.75)
CSI_VSYNC: J17.14 R245.1 R246.1 U11.AA3 U34.4 | length 50.2
  Top w0.119: J17.14@52,66.8 52,67.75 52.15,67.9 ; 52.15,67.9 v1(52.6,67.9) 52.657,67.9 v1@52.6,67.843 ; v1(62.5,52.1) 62.55,52.1 U11.AA3@63.05,51.6 ; v1(75.3,61.3) R246.1@75.3,62.12 ; R245.1@77.98,61 78.5,61 78.7,61.2 v1(78.7,61.5) U34.4@78.7,62.15
  Signal_3 w0.127: v1(62.5,52.1) 63.337,52.1 64.467,53.229 65.195,53.229 66.202,54.237 67.204,54.237 67.308,54.132 67.698,54.132 68.521,54.954 68.521,55.27 68.779,55.529 68.795,55.529 69.465,56.2 75.543,56.2 75.713,56.029 76.029,56.029 76.4,56.4 76.4,60.185 75.3,61.285 v1(75.3,61.3) 75.75,61.75 77.5,61.75 77.75,61.5 v1(78.7,61.5)
  Signal_8 w0.127: v1(52.6,67.9) 52.6,67.211 53.673,66.137 53.673,65.096 55.53,63.239 55.53,63.205 55.608,63.127 55.608,62.927 56.305,62.229 56.404,62.229 61.308,57.326 61.308,54.026 62.5,52.835 v1(62.5,52.1)
DISP_5V_PWR/IO29: Q11.G R252.2 U27.39 | length 74.8
  Top w0.125: U27.39@55.45,30.5 56.032,30.5 56.632,29.9 v2(57.05,29.9)
  Signal_8 w0.125: v3(56.8,35.4) 56.932,35.532 56.932,37.218 56.78,37.37 56.78,38.194 57.793,39.207 57.793,40.801 58.626,41.634 58.626,42.405 58,43.031 58,44.67 58.93,45.6 58.93,46.43 59.4,46.9 59.4,47.6 57.78,49.22 57.78,58.92 v1(57.2,59.5)
  Signal_7 w0.125: v2(26.1,58.5) 26.1,58.469 29.563,55.006 34.025,55.006 35.342,53.689 42.996,53.689 43.426,54.119 44.524,54.119 46.991,56.586 48.227,56.586 50.83,59.19 50.83,59.674 51.099,59.942 51.726,59.942 52.569,59.1 53.7,59.1 54.473,59.873 56.827,59.873 v1(57.2,59.5)
  Bottom w0.125: v2(26.1,58.5) Q11.G@26.81,58.5 28.183,58.5 28.5,58.183 R252.2@28.5,57.68 ; v3(56.8,35.4) 56.48,35.08 56.48,34.426 57.039,33.868 57.073,33.868 57.318,33.623 57.318,32.761 56.68,32.124 56.68,31.776 57.05,31.407 v2(57.05,29.9)
EMMC/SD#: R38.1 U11.V14 U33.6 U34.6 | length 40.4
  Top w0.119: v1(66.225,36.995) U11.V14@66.86,37.63 ; U33.6@78.7,59.75 78.7,60.2 v1(79.1,60.6) ; U34.6@78.7,63.45 78.8,63.55 v1(78.8,64.1)
  Signal_8 w0.127: v1(66.225,36.995) 66.764,37.534 66.764,39.052 66.948,39.236 66.948,40.41 66.764,40.594 66.764,43.536 66.155,44.145 66.03,44.145 65.755,44.42 65.755,44.81 66.329,45.384 66.48,45.384 66.764,45.669 66.764,50.482 67.058,50.777 67.058,51.014 67.759,51.715 68.773,51.715 71.362,54.305 71.5,54.305 71.776,54.58 71.776,57.376 74.15,59.75 78.25,59.75 v1(79.1,60.6)
  Bottom w0.119: R38.1@66.2,37.72 66.225,37.695 v1(66.225,36.995) ; v1(78.8,64.1) 79.4,63.5 79.4,60.9 v1(79.1,60.6)
EMMC_CLK: R246.2 U2.M6 U34.1 | length 8.4
  Top w0.119: v2(69.5,62.75) 69.5,62.3 69.593,62.207 69.793,62.207 U2.M6@70,62 ; v1(74.5,63.1) 74.52,63.08 R246.2@75.3,63.08 75.67,63.45 U34.1@76.5,63.45
  Signal_3 w0.127: v2(69.5,62.75) 71.1,62.75 71.45,63.1 v1(74.5,63.1)
EMMC_CMD: R244.2 U2.M5 U33.1 | length 10
  Top w0.119: v2(69.5,61.75) 69.75,61.5 U2.M5@70,61.5 ; v1(75.4,60.4) R244.2@75.4,59.68 75.47,59.75 U33.1@76.5,59.75
  Signal_3 w0.127: v2(69.5,61.75) 70.8,60.45 70.8,60.2 71.7,59.3 74.3,59.3 v1(75.4,60.4)
EMMC_PWR/IO8: Q6.G R186.2 U27.15 | length 54.2
  Top w0.119: U27.15@48.55,34 48,34 47.251,34.749 47.251,37.53 46.941,37.841 46.941,38.666 46.556,39.051 46.556,40.056 v2(48.6,42.1)
  Signal_3 w0.127: v2(50.4,59.4) 50.4,59.35 50.918,58.832 53.682,58.832 55.05,60.2 58.5,60.2 62.929,55.771 64.949,55.771 66.191,54.529 66.695,54.529 66.97,54.805 66.97,55.001 67.353,55.384 67.353,55.673 67.681,56 v1(68.6,56)
  Signal_8 w0.127: v2(48.6,42.1) 48.281,42.418 47.711,42.418 47.47,42.659 47.47,43.076 49,44.605 49,49.25 48.313,49.937 48.313,56.672 50.4,58.759 v2(50.4,59.4)
  Bottom w0.119: v1(68.6,56) 68.6,56.72 69.83,56.72 Q6.G@69.86,56.75
ENET1_INT#: R53.1 U11.Y19 U16.14 | length 66.4
  Top w0.119: v1(63.75,30.75) 63.79,30.75 U11.Y19@64.32,31.28
  Signal_8 w0.127: v2(28.9,41.7) 30.178,40.421 30.178,36.865 29.228,35.915 29.228,33.423 28.579,32.774 28.579,32.426 28.826,32.179 29.174,32.179 29.215,32.22 29.479,32.22 30.22,31.48 30.22,29.174 v2(30.203,29.157)
  Signal_7 w0.127: v2(28.9,41.7) 29.172,41.7 34.394,36.478 37.515,36.478 38.654,35.339 38.654,32.451 39.573,31.532 43.131,31.532 43.966,32.368 46.111,32.368 46.755,33.011 47.945,33.011 48.627,32.33 54.712,32.33 56.453,34.07 59.489,34.07 60.813,32.746 60.813,30.79 61.704,29.9 62.94,29.9 63.75,30.71 v1(63.75,30.75)
  Bottom w0.119: U16.14@25.9,29 26.8,29 27.3,29.5 R53.1@28.02,29.5 28.62,28.9 30.3,28.9 30.203,28.997 v2(30.203,29.157)
ENET1_RX_DATA0: R58.2 R62.1 U11.L21 U16.8 | length 78.8
  Top w0.119: v1(73.7,28) 75.01,28 U11.L21@75.75,28.74
  Signal_7 w0.127: v3(21.9,34.5) 21.492,34.092 21.492,33.308 21.815,32.985 23.585,32.985 24.75,31.82 25.074,31.82 26.24,30.655 26.24,27.84 ; 26.2,27.8 27.821,26.179 29.974,26.179 30.249,26.454 32.461,26.454 37.661,21.254 42.044,21.254 43.534,19.764 50.361,19.764 50.73,20.132 55.949,20.132 56.56,19.521 58.446,19.521 61.079,22.155 61.079,22.443 62.268,23.631 65.406,23.631 65.546,23.49 72.79,23.49 74.5,25.2 74.5,27.2 v1(73.7,28)
  Bottom w0.119: R58.2@21.873,35.229 R62.1@23.123,35.229 22.615,34.721 22.615,34.366 23.281,33.7 23.574,33.7 23.917,33.357 23.917,31.127 23.673,30.884 23.477,30.884 23.25,30.657 U16.8@23.25,30.15 ; v3(21.9,34.5) R58.2@21.9,35.202
ENET1_RX_DATA1: R59.2 R63.1 U11.E21 U16.7 | length 87.7
  Top w0.119: v1(82.9,28.6) 83.04,28.74 U11.E21@83.37,28.74
  Signal_7 w0.127: v2(23.5,31.3) 23.395,31.3 22.763,31.931 21.737,31.931 19.25,29.445 19.25,25.548 22.979,21.819 26.846,21.819 29.16,19.505 41.997,19.505 43.008,18.494 50.52,18.494 50.988,18.026 59.022,18.026 61.56,20.563 62.617,20.563 63.574,21.521 63.574,22.069 63.866,22.361 64.88,22.361 65.02,22.22 79.813,22.22 82.9,25.307 v1(82.9,28.6)
  Bottom w0.119: U16.7@22.75,30.15 22.75,30.35 22,31.1 R63.1@22,32.02 R59.2@23.25,32.02 23.25,31.55 v2(23.5,31.3)
ENET1_RX_EN: R57.2 R61.1 U11.K21 U16.11 | length 73
  Top w0.119: v1(73.9,26.8) 74.809,26.8 75.527,26.082 77.973,26.082 78.418,26.527 78.418,27.182 77.4,28.2 77.4,28.4 77.06,28.74 U11.K21@77.02,28.74
  Signal_7 w0.127: v2(27.7,33.6) 28.595,33.6 31.453,30.742 31.453,28.129 32.961,26.62 33.674,26.62 36.437,23.857 36.437,22.837 37.767,21.508 42.149,21.508 43.639,20.018 50.256,20.018 50.625,20.386 56.054,20.386 56.665,19.775 58.341,19.775 58.933,20.367 58.933,21.767 59.582,22.416 60.694,22.416 62.162,23.885 65.511,23.885 65.652,23.744 72.41,23.744 73.97,25.305 73.97,26.729 v1(73.9,26.8)
  Bottom w0.119: U16.11@24.75,30.15 24.75,30.65 24.837,30.737 25.174,30.737 25.562,31.126 25.562,31.462 25.75,31.65 R57.2@25.75,32.02 R61.1@27,32.02 27.42,32.02 27.6,32.2 27.6,33.5 27.534,33.565 27.591,33.622 27.613,33.6 v2(27.7,33.6)
ENET1_RX_ER: R56.2 R60.1 U11.J21 U16.10 | length 76.1
  Top w0.119: v1(72.9,26.7) 73.269,26.33 74.094,26.33 74.233,26.47 74.731,26.47 75.4,25.8 78.1,25.8 78.7,26.4 78.7,28.33 U11.J21@78.29,28.74
  Signal_7 w0.127: v2(28.3,34.2) 29.478,34.2 31.8,31.878 31.8,28.141 33.065,26.876 33.924,26.876 36.854,23.946 36.854,22.78 37.872,21.762 42.254,21.762 43.745,20.272 47.59,20.272 48.339,21.02 49.12,21.02 49.5,20.64 56.16,20.64 56.771,20.029 57.229,20.029 58.6,21.4 58.6,21.85 59.42,22.67 60.589,22.67 62.057,24.139 65.616,24.139 65.757,23.998 70.433,23.998 72.9,26.466 v1(72.9,26.7)
  Bottom w0.119: U16.10@24.25,30.15 24.25,30.75 24.48,30.98 24.674,30.98 24.677,30.983 25.072,30.983 25.316,31.227 25.316,31.576 25.254,31.639 25.254,33.342 25.396,33.485 25.822,33.485 26.066,33.729 26.066,34.786 R56.2@25.623,35.229 R60.1@26.873,35.229 27.271,35.229 v2(28.3,34.2)
ENET1_TX_CLK: U11.F21 U16.5 | length 77.4
  Top w0.119: U11.F21@82.1,28.74 82.4,29.04 v1(82.4,29.4)
  Signal_7 w0.127: v2(21.4,29.1) 21.4,28.85 22.1,28.15 22.1,23.057 23.084,22.073 27,22.073 29.314,19.759 42.102,19.759 43.113,18.748 50.625,18.748 51.093,18.28 58.916,18.28 61.454,20.817 62.512,20.817 63.32,21.626 63.32,22.274 63.661,22.615 64.985,22.615 65.126,22.474 78.882,22.474 82.57,26.163 82.57,28.195 82.33,28.436 82.33,29.329 v1(82.4,29.4)
  Bottom w0.119: v2(21.4,29.1) 22,29.1 U16.5@22.1,29
ENET1_TX_DATA0: U11.D21 U16.17 | length 70.5
  Top w0.119: v1(82.1,28) 84.34,28 84.64,28.3 U11.D21@84.64,28.74
  Signal_7 w0.127: v3(30.1,25.5) 30.1,21.641 31.728,20.013 42.207,20.013 43.219,19.002 51.036,19.002 51.405,19.37 55.633,19.37 56.244,18.759 59.037,18.759 61.349,21.071 61.885,21.071 62.479,21.666 62.479,22.061 63.287,22.869 65.09,22.869 65.231,22.728 77.2,22.728 78.3,23.828 78.3,24.7 80.54,26.94 81.04,26.94 v1(82.1,28)
  Bottom w0.119: U16.17@25.9,27.5 26.8,27.5 27.248,27.052 27.248,26.472 27.769,25.952 29.105,25.952 29.38,25.676 29.674,25.676 29.85,25.5 v3(30.1,25.5)
ENET1_TX_DATA1: U11.H21 U16.18 | length 65.8
  Top w0.119: v1(78.9,29.7) 79.56,29.04 U11.H21@79.56,28.74
  Signal_7 w0.127: v3(29.4,25.2) 29.4,25.705 29.621,25.925 30.079,25.925 30.354,26.2 32.1,26.2 35.5,22.8 35.5,21.7 36.2,21 41.939,21 43.429,19.51 50.466,19.51 50.835,19.878 55.844,19.878 56.455,19.267 58.827,19.267 61.139,21.579 61.674,21.579 61.92,21.826 61.92,22.22 63.077,23.377 65.301,23.377 65.441,23.236 74.12,23.236 76.4,25.516 76.4,27.5 77.5,28.6 78.5,28.6 78.9,29 v1(78.9,29.7)
  Bottom w0.119: U16.18@25.9,27 26.364,27 27.664,25.7 29,25.7 29.4,25.3 v3(29.4,25.2)
ENET1_TX_EN: U11.G21 U16.16 | length 69.6
  Top w0.119: U11.G21@80.83,28.74 81.29,28.74 81.504,28.954 v1@81.504,29.186
  Signal_7 w0.127: v3(30.8,25.5) 30.8,24.5 30.5,24.2 30.5,21.6 31.833,20.267 42.312,20.267 43.324,19.256 50.572,19.256 50.941,19.624 55.739,19.624 56.35,19.013 58.932,19.013 61.244,21.325 61.779,21.325 62.225,21.771 62.225,22.166 63.182,23.123 65.195,23.123 65.336,22.982 76.677,22.982 77.484,23.789 77.484,25.775 80.079,28.371 80.079,28.374 80.326,28.62 80.329,28.62 80.409,28.7 81.078,28.7 v1(81.504,29.126)
  Bottom w0.119: U16.16@25.9,28 27,28 27.5,27.5 27.5,26.577 27.873,26.204 29.247,26.204 29.522,25.928 30.372,25.928 v3(30.8,25.5)
ENET2_INT#: R154.1 U11.U19 U24.14 | length 60.6
  Top w0.119: v1(67.5,31.2) 68.05,31.2 U11.U19@68.13,31.28
  Signal_3 w0.127: v2(27.626,48.427) 27.933,48.121 29.674,48.121 29.728,48.066 36.2,48.066 v2(36.2,47.9)
  Signal_7 w0.127: v2(36.2,47.9) 34.917,46.617 34.917,42.336 36.682,40.571 37.399,40.571 37.685,40.858 39.079,40.858 41.737,38.2 45.828,38.2 47.998,36.029 51.979,36.029 52.447,36.497 52.447,37.155 52.7,37.409 52.7,38.285 53.927,39.512 58.151,39.512 58.754,38.908 59.726,38.908 60.978,37.655 60.978,37.296 62.004,36.271 62.745,36.271 63.2,35.815 63.2,35.545 63.819,34.926 63.88,34.926 64.231,34.575 64.231,33.229 64.715,32.744 65.434,32.744 65.726,32.453 65.726,31.749 66.03,31.445 66.482,31.445 66.726,31.2 v1(67.5,31.2)
  Bottom w0.119: U24.14@26.539,47.657 27.019,47.657 v2@27.708,48.346 ; v2(27.626,48.427) 27.626,48.606 R154.1@28.02,49
ENET2_RX_DATA0: R10.1 R18.1 R160.2 R164.1 U11.W17 | length 99.8
  Top w0.119: v2(17.5,33.2) 18.162,33.2 19.108,32.254 R18.1@23.82,32.254 ; v2(20.75,52.519) 20.75,52.05 21.2,51.6 R10.1@22.32,51.6 ; v1(65,33.5) 65.07,33.5 65.17,33.4 U11.W17@65.59,33.82
  Signal_8 w0.127: v2(17.5,33.2) 17.5,34.3 18.377,35.177 18.524,35.177 19,35.653 19,36.9 20.225,38.125 20.225,43.783 22.32,45.878 22.32,48.422 21.8,48.942 21.8,51.469 v2(20.75,52.519)
  Signal_7 w0.127: v2(20.75,52.519) 20.769,52.519 21.17,52.92 23.128,52.92 25.082,54.875 26.179,54.875 26.674,54.379 26.674,52.676 27.642,51.708 33.41,51.708 34.375,50.743 34.375,49.8 35.029,49.146 36.267,49.146 36.975,48.438 36.975,47.515 35.425,45.966 35.425,42.547 36.893,41.079 37.189,41.079 37.475,41.366 39.29,41.366 40.755,39.9 44.846,39.9 47.217,37.529 48.114,37.529 48.305,37.72 49.97,37.72 52.27,40.02 58.361,40.02 58.965,39.416 59.936,39.416 61.887,37.466 62.61,37.466 62.886,37.19 62.886,37.129 63.49,36.525 63.995,36.525 64.41,36.11 64.41,35.605 65.089,34.926 65.15,34.926 65.426,34.65 65.426,33.826 65.172,33.572 65,33.745 v1(65,33.5)
  Bottom w0.119: v2(20.75,52.519) 20.75,52.538 R164.1@21.639,53.427 R160.2@22.889,53.427
ENET2_RX_DATA1: R9.1 R19.2 R161.2 R165.1 U11.W19 | length 72.9
  Top w0.119: v2(20.973,50.927) 21.373,50.927 21.9,50.4 R9.1@22.32,50.4 ; R19.2@32.096,33.08 32.096,33.596 v2(32.35,33.85) ; v1(64.955,30.645) U11.W19@65.59,31.28
  Signal_8 w0.127: v2(32.35,33.85) 32.35,34.746 31.151,35.946 31.151,36.551 33.676,39.075 34.475,39.075 34.633,39.233 v2(34.633,39.867)
  Signal_7 w0.127: v2(20.973,50.927) 25.955,50.927 26.19,50.692 27.203,50.692 28.12,49.774 28.12,46.145 32.779,41.486 32.779,40.255 33.705,39.329 34.095,39.329 v2(34.633,39.867) 35.316,39.184 37.712,39.184 38.496,38.4 38.895,38.4 39.62,37.674 39.62,37.535 42.555,34.6 43.854,34.6 44.7,33.754 45.174,33.754 45.935,34.515 52.933,34.515 53.965,35.546 55.219,35.546 56.452,36.779 59.087,36.779 60.739,35.127 60.739,34.257 61.829,33.167 61.829,32.771 62.215,32.386 62.61,32.386 63.267,31.728 64.155,31.728 64.701,31.183 64.806,31.183 64.955,31.034 v1(64.955,30.645)
  Bottom w0.119: v2(20.973,50.927) R165.1@21.639,50.927 R161.2@22.889,50.927
ENET2_RX_EN: R159.2 R163.1 U11.V20 U24.11 | length 61.9
  Top w0.119: v1(66.225,29.375) U11.V20@66.86,30.01
  Signal_7 w0.127: v2(27.1,50.2) 27.1,49.7 27.279,49.521 27.279,48.785 26.6,48.105 26.6,45.985 27.555,45.03 28.736,45.03 30.4,43.365 30.4,42.275 33.745,38.93 37.454,38.93 38.729,37.655 38.729,37.177 42.526,33.38 43.074,33.38 43.077,33.382 45.691,33.382 46.439,34.129 54.495,34.129 55.4,35.035 55.4,35.368 56.557,36.525 58.981,36.525 60.485,35.022 60.485,34.152 61.575,33.061 61.575,31.692 61.898,31.37 63.345,31.37 63.45,31.474 64.05,31.474 64.474,31.05 64.474,30.326 64.625,30.175 65.426,30.175 v1(66.225,29.375)
  Bottom w0.119: U24.11@25.389,48.807 25.389,49.689 25.889,50.189 R159.2@25.889,50.927 R163.1@27.139,50.927 27,50.788 27.1,50.688 v2(27.1,50.2)
ENET2_RX_ER: R158.2 R162.1 U11.V19 U24.10 | length 66.8
  Top w0.119: v1(66.225,30.645) U11.V19@66.86,31.28
  Signal_7 w0.127: v2(25.9,54.2) 25.146,53.446 25.146,52.4 26.6,50.946 27.308,50.946 28.374,49.879 28.374,46.326 31.478,43.222 32.2,43.222 33.795,41.628 33.795,41.305 35.662,39.438 37.817,39.438 38.001,39.255 39.09,39.255 41.717,36.628 41.717,35.989 42.726,34.98 44.392,34.98 44.829,35.417 45.178,35.417 45.826,34.769 52.828,34.769 53.859,35.8 54.75,35.8 55.174,36.225 55.174,36.84 55.505,37.17 55.755,37.17 57.055,38.47 57.755,38.47 60.993,35.232 60.993,34.362 61.879,33.477 62.589,33.477 62.775,33.29 62.775,32.579 63.372,31.982 64.26,31.982 64.806,31.437 65.32,31.437 66.111,30.645 v1(66.225,30.645)
  Bottom w0.119: U24.10@24.889,48.807 24.889,49.689 25.1,49.9 25.1,54.18 R158.2@25.08,54.2 v2(25.9,54.2)
ENET2_TX_CLK: U11.V18 U24.5 | length 74.1
  Top w0.119: v1(66.225,31.915) U11.V18@66.86,32.55
  Signal_7 w0.127: v2(21.9,47.7) 20.552,49.048 20.552,51.152 21,51.6 22.705,51.6 25.726,54.621 26.074,54.621 26.42,54.274 26.42,52.285 27.251,51.454 33.305,51.454 34.121,50.638 34.121,49.695 34.924,48.892 36.162,48.892 36.721,48.333 36.721,47.621 35.171,46.072 35.171,42.441 36.788,40.825 37.294,40.825 37.58,41.112 39.185,41.112 41.042,39.255 45.132,39.255 47.607,36.779 49.429,36.779 50.8,38.15 50.8,38.165 52.4,39.766 58.256,39.766 58.859,39.162 59.831,39.162 61.232,37.761 61.232,37.512 62.22,36.525 63.131,36.525 63.385,36.271 63.889,36.271 64.06,36.1 64.06,36.08 64.156,35.984 64.156,35.009 64.485,34.68 64.485,33.35 64.836,32.998 65.54,32.998 66.225,32.313 v1(66.225,31.915)
  Bottom w0.119: v2(21.9,47.7) 21.943,47.657 U24.5@22.739,47.657
ENET2_TX_DATA0: U11.W18 U24.17 | length 51.4
  Top w0.119: v1(65,32) 65.04,32 U11.W18@65.59,32.55
  Signal_7 w0.127: v2(34.4,41.9) 34.4,41.059 35.767,39.692 37.597,39.692 38.001,40.096 38.608,40.096 42.858,35.846 45.108,35.846 45.931,35.023 52.723,35.023 53.754,36.054 54.645,36.054 54.92,36.33 54.92,36.945 55.4,37.424 55.65,37.424 56.95,38.724 57.86,38.724 61.247,35.337 61.247,34.467 61.984,33.731 62.694,33.731 63.029,33.395 63.029,32.71 63.503,32.236 64.366,32.236 64.602,32 v1(65,32)
  Bottom w0.119: U24.17@26.539,46.157 26.991,46.157 27.148,46 27.148,45.438 27.556,45.03 28.87,45.03 29.266,44.634 29.266,43.386 29.903,42.749 32.903,42.749 33.313,42.339 33.961,42.339 v2(34.4,41.9)
ENET2_TX_DATA1: U11.W20 U24.18 | length 51.6
  Top w0.119: v1(65,29.5) 65.08,29.5 U11.W20@65.59,30.01
  Signal_7 w0.127: v1(28.8,44.3) 30.009,43.091 30.009,42.307 33.64,38.676 37.349,38.676 38.475,37.55 38.475,37.072 42.421,33.126 43.179,33.126 43.182,33.128 45.797,33.128 46.544,33.875 54.6,33.875 55.654,34.929 55.654,35.263 56.662,36.271 58.876,36.271 60.231,34.917 60.231,34.046 61.321,32.956 61.321,31.587 61.793,31.116 63.45,31.116 63.555,31.22 63.945,31.22 64.22,30.945 64.22,30.22 64.941,29.5 v1(65,29.5)
  Bottom w0.119: U24.18@26.539,45.657 26.539,45.361 27.122,44.778 28.472,44.778 28.8,44.45 v1(28.8,44.3)
ENET2_TX_EN: U11.V17 U24.16 | length 53.1
  Top w0.119: v1(66.225,33.185) U11.V17@66.86,33.82
  Signal_7 w0.127: v2(36.2,42.9) 36.5,43.2 38.8,43.2 40.42,41.58 40.42,41.235 41.255,40.4 45.549,40.4 47.074,38.876 47.359,38.876 48.096,38.139 49.45,38.139 49.9,38.589 49.9,39.15 51.024,40.274 57.152,40.274 57.816,40.938 60.262,40.938 61.627,39.573 61.627,38.084 61.992,37.72 63.206,37.72 63.385,37.541 63.859,37.541 64.15,37.25 64.15,37.201 64.156,37.195 64.156,36.745 64.629,36.271 65.129,36.271 65.476,35.924 65.476,34.959 65.68,34.755 65.68,34.335 66.225,33.79 v1(66.225,33.185)
  Bottom w0.119: U24.16@26.539,46.657 27.243,46.657 27.4,46.5 27.4,45.6 27.721,45.279 28.987,45.279 29.518,44.748 29.518,43.482 30,43 33,43 33.415,42.585 34.272,42.585 34.587,42.9 v2(36.2,42.9)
